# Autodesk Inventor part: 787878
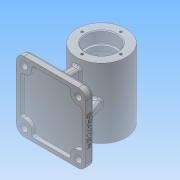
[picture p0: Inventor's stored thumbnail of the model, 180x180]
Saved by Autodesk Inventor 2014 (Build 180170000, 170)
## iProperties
Created: 2019-06
Part Number: 787878
Material: 일반
Document SubType Name: Modeling
Designer: NET
Density: 1 g/cm^3
Appearance: 기본값
Author: NET
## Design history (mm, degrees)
sketch "스케치3"
  geometry: L1 (-45, 45)-(45, 45); L2 (45, 45)-(45, -45); L3 (45, -45)-(-45, -45); L4 (-45, -45)-(-45, 45); L5 (-45, 45)-(45, -45); L6 (45, 45)-(-45, -45); 1 further point
  constraints: 12 end point, 2 midpoint, 2 parallel, 1 horizontal, 1 perpendicular
  dimensions: "d5" = 90 distance of L2.end L3.end; "d6" = 90 distance of L1.end L2.end
extrude "돌출2" new body sketch "스케치3" distance "d7" = 10; taper "d8" = 0 deg
node "작업 평면1"
sketch "스케치4"
  geometry: L1 (0, 0)-(0, 10) reference; L2 (0, 10)-(90, 10) reference; L3 (90, 10)-(90, 0) reference; L4 (90, 0)-(0, 0) reference; L5 (45, 0)-(45, 65); L6 (0, 65)-(90, 65); L7 (0, 65)-(0, 97); L8 (0, 97)-(90, 97); L9 (90, 97)-(90, 65)
  constraints: 10 end point, 3 perpendicular, 1 horizontal, 1 midpoint, 1 parallel
  dimensions: "d9" = 65 distance of L5.end L5.start; "d10" = 90 distance of L6.start L6.end; "d11" = 64 diameter of L8 L6
revolve "회전1" sketch "스케치4" stored, may be unused: angle "d12" = 90 deg
sketch "스케치5"
  geometry: L1 (-45, -45)-(45, -45) reference; L2 (-45, 45)-(-45, -45) reference; L3 (-45, -45)-(-45, 45) reference; L4 (-45, 45)-(45, 45) reference; L5 (45, 45)-(45, -45) reference; L6 (45, -45)-(-45, -45) reference; L7 (-5, -35)-(5, -35); L8 (5, -35)-(5, 35); L9 (5, 35)-(-5, 35); L10 (-5, 35)-(-5, -35); 5 further points
  constraints: 8 end point, 4 midpoint, 2 parallel, 1 horizontal, 1 horizontal alignment, 1 perpendicular, 1 vertical alignment
  dimensions: "d13" = 10 distance of L8.end L9.end; "d14" = 70 distance of L9.end L7.start
extrude "돌출3" join sketch "스케치5" stored distance "d15" = 10; taper "d16" = 0 deg
node "작업 평면2"
sketch "스케치6"
  geometry: L1 (90, 10)-(90, 0) reference; L2 (90, 0)-(0, 0) reference; L3 (0, 0)-(0, 10) reference; L4 (0, 10)-(40, 10) reference; L5 (40, 10)-(40, 33.393) reference; L6 (50, 33.393)-(50, 10) reference; L7 (50, 10)-(90, 10) reference; L8 (10, 10)-(21.942, 42.811); A1 r 32 centre (45, 65) between (50, 33.393) and (40, 33.393) reference; 1 further point
  constraints: 2 end point, 1 point on circle, 1 point on line
  dimensions: "d17" = 110 deg angle of L4 L8; "d18" = 10 distance of L3.end L8.start
feature "리브1" sketch "스케치6" dims "d19" = 1, "d20" = 10, "d21" = 0, "d22" = 0, "d23" = 1, "d24" = 1
node "작업 평면3"
sketch "스케치7"
  geometry: L1 (80, 10)-(90, 10) reference; L2 (90, 10)-(90, 0) reference; L3 (90, 0)-(0, 0) reference; L4 (0, 0)-(0, 10) reference; L5 (0, 10)-(10, 10) reference; L6 (10, 10)-(10, 33) reference; L7 (10, 33)-(0, 33) reference; L8 (0, 33)-(0, 97) reference; L9 (0, 97)-(90, 97) reference; L10 (90, 97)-(90, 33) reference; L11 (90, 33)-(80, 33) reference; L12 (80, 33)-(80, 10) reference; L13 (0, 65)-(90, 65); L14 (0, 85)-(15, 85); L15 (15, 85)-(15, 82); L16 (15, 82)-(21, 82); L17 (21, 82)-(21, 90); L18 (21, 90)-(69, 90); L19 (69, 90)-(69, 82); L20 (69, 82)-(75, 82); L21 (75, 82)-(75, 85); L22 (75, 85)-(90, 85); 1 further point
  constraints: 20 end point, 7 parallel, 2 midpoint, 2 perpendicular, 2 point on line
  dimensions: "d25" = 15 distance of L21.end L22.end; "d26" = 15 distance of L14.start L14.end; "d27" = 48 distance of L17.end L18.end; "d28" = 6 distance of L15.end L16.end; "d29" = 40 diameter of L14 L13; "d30" = 40 diameter of L22 L13; "d31" = 50 diameter of L18 L13; "d32" = 34 diameter of L20 L13; "d33" = 34 diameter of L16 L13
revolve "회전2" sketch "스케치7" stored, may be unused: angle "d34" = 90 deg
node "작업 평면4"
sketch "스케치8"
  geometry: L1 (-32, -45)-(32, -45) reference; L2 (-32, 45)-(32, 45) reference; L3 (23.058, -5)-(23.058, 5) reference; L4 (23.058, 5)-(5, 5) reference; L5 (5, 5)-(5, 35) reference; L6 (5, 35)-(-5, 35) reference; L7 (-5, 35)-(-5, 5) reference; L8 (-5, 5)-(-23.058, 5) reference; L9 (-23.058, 5)-(-23.058, -5) reference; L10 (-23.058, -5)-(-5, -5) reference; L11 (-5, -5)-(-5, -35) reference; L12 (-5, -35)-(5, -35) reference; L13 (5, -35)-(5, -5) reference; L14 (5, -5)-(23.058, -5) reference; C1 r 5 at (0, 0); 2 further points
  constraints: 1 centre point, 1 midpoint, 1 vertical alignment
  dimensions: "d36" = 10 diameter of C1; "d37" = 45 distance from line of L2 C1.centre
extrude "돌출4" join sketch "스케치8" stored distance "d38" = 10; taper "d39" = 0 deg
sketch "스케치9"
  geometry: C1 r 5 at (0, 0) reference; 1 further point
  constraints: 1 coincident
hole "구멍1" sketch "스케치9" at (0, 0) diameter "d40" = 4.917; stored, may be unused: countersink angle "d44" = 90 deg, drill point angle "d46" = 118 deg; dims "d41" = 6, "d42" = 4, "d43" = 2, "d45" = 17.25
sketch "스케치10"
  geometry: L1 (45, -65)-(-45, -65) reference; L2 (-45, -65)-(-45, -55) reference; L3 (-45, -55)-(45, -55) reference; L4 (45, -55)-(45, -65) reference; C1 r 20 at (0, 0) reference; C2 r 20 at (0, 0) reference; C3 r 32 at (0, 0) reference; 2 further points
  constraints: 1 vertical alignment
  dimensions: "d47" = 25 distance of C1.centre point (0, 25)
hole "구멍2" sketch "스케치10" at (0, 25) diameter "d48" = 3.242; stored, may be unused: countersink angle "d52" = 90 deg, drill point angle "d54" = 118 deg; dims "d49" = 7, "d50" = 4, "d51" = 2, "d53" = 9
fillet "모깎기2" dims "d61" = 10
sketch "스케치13"
  geometry: L1 (-26.34, 40)-(26.34, 40); L2 (40, 26.34)-(40, -26.34); L3 (26.34, -40)-(-26.34, -40); L4 (-40, -26.34)-(-40, 26.34); L5 (-40, 40)-(40, -40); L6 (40, 40)-(-40, -40); A1 r 10 centre (35, -35) between (35, -45) and (45, -35) reference; A2 r 10 centre (35, 35) between (45, 35) and (35, 45) reference; A3 r 10 centre (-35, 35) between (-35, 45) and (-45, 35) reference; A4 r 10 centre (-35, -35) between (-45, -35) and (-35, -45) reference; A5 r 10 centre (35, 35) between (40, 26.34) and (26.34, 40); A6 r 10 centre (35, -35) between (26.34, -40) and (40, -26.34); A7 r 10 centre (-35, -35) between (-40, -26.34) and (-26.34, -40); A8 r 10 centre (-35, 35) between (-26.34, 40) and (-40, 26.34); 1 further point
  constraints: 12 end point, 8 point on circle, 4 centre point, 4 coincident, 2 midpoint, 2 parallel, 1 horizontal, 1 perpendicular
  dimensions: "d62" = 80 distance of L5.end L6.end; "d63" = 80 distance of L6.start L5.end; "d65" = 20 diameter of A5; "d66" = 20 diameter of A6; "d67" = 20 diameter of A7; "d68" = 20 diameter of A8
extrude "돌출6" cut sketch "스케치13" distance "d71" = 5; taper "d72" = 0 deg
fillet "모깎기3" dims "d73" = 3
sketch "스케치15"
  geometry: L1 (-35, 45)-(35, 45) reference; L2 (45, 35)-(45, -35) reference; L3 (35, -45)-(-35, -45) reference; L4 (-45, -35)-(-45, 35) reference; L5 (-35, 5)-(-5, 5) reference; L6 (-5, 5)-(-5, 35) reference; L7 (-5, 35)-(5, 35) reference; L8 (5, 35)-(5, 5) reference; L9 (5, 5)-(35, 5) reference; L10 (35, 5)-(35, -5) reference; L11 (35, -5)-(5, -5) reference; L12 (5, -5)-(5, -35) reference; L13 (5, -35)-(-5, -35) reference; L14 (-5, -35)-(-5, -5) reference; L15 (-5, -5)-(-35, -5) reference; L16 (-35, -5)-(-35, 5) reference; C1 r 4.5 at (-35, 35); C2 r 4.5 at (35, 35); C3 r 4.5 at (35, -35); C4 r 4.5 at (-35, -35); A1 r 10 centre (-35, 35) between (-35, 45) and (-45, 35) reference; A2 r 10 centre (35, 35) between (45, 35) and (35, 45) reference; A3 r 10 centre (35, -35) between (35, -45) and (45, -35) reference; A4 r 10 centre (-35, -35) between (-45, -35) and (-35, -45) reference; 1 further point
  constraints: 4 centre point, 4 coincident
  dimensions: "d74" = 9 diameter of C1; "d75" = 9 diameter of C2; "d76" = 9 diameter of C3; "d77" = 9 diameter of C4
extrude "돌출7" cut sketch "스케치15" stored distance "d78" = 5; taper "d79" = 0 deg
fillet "모깎기4" dims "d80" = 3
fillet "모깎기5" dims "d81" = 3
fillet "모깎기6" dims "d82" = 3
fillet "모깎기7" dims "d83" = 3
fillet "모깎기8" dims "d84" = 3
chamfer "모따기1" distance "d85" = 1; stored, may be unused: second distance "d86" = 2, angle "d87" = 45 deg
fillet "모깎기9" dims "d88" = 0.6
fillet "모깎기10" dims "d89" = 3
fillet "모깎기11" dims "d90" = 2
node "작업 평면5"
sketch "스케치16"
  geometry: L1 (0, 0)-(-10, 0) reference; L2 (-10, 7)-(-10, 0) reference; 2 further points
  constraints: 1 other
  dimensions: "d92" = 4 distance from line of L1 point (35, 4); "d93" = 45 distance from line of L2 point (35, 4)
feature "엠보싱1" sketch "스케치16" dims "d94" = 0.5, "d95" = 0
node "솔리드2"
mirror "대칭1"
pattern_circular "원형 패턴1" dims angle "d56" = 360 deg
mirror "대칭2"
node "투영된 루프1"
node "절단 모서리 투영1"
node "절단 모서리 투영2"
node "절단 모서리 투영3"
node "절단 모서리 투영4"
node "절단 모서리 투영5"
node "절단 모서리 투영7"
other parameters: "d91" = 0
